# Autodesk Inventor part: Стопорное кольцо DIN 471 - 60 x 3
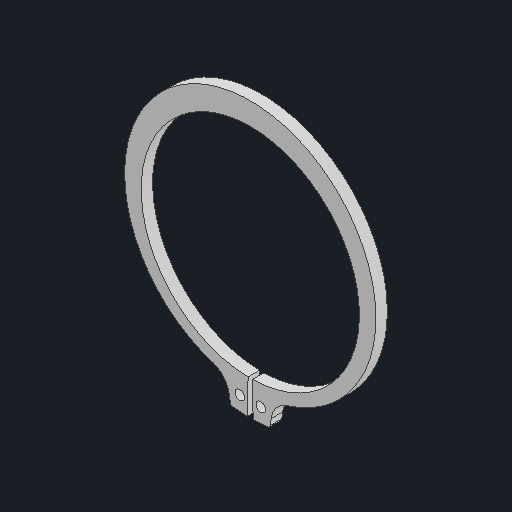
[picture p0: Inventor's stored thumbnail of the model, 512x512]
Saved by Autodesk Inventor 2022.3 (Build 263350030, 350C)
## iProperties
Created: 2020-09
Part Number: Стопорное кольцо DIN 471 - 60 x 3
Material: Типовые
Document SubType Name: Modeling
Designer: Карташов
Density: 1 g/cm^3
Appearance: По умолчанию
Title: D:\мои документы\Ирина\_WorldSkills\2020_09 ФНЧ\Module A\Участникам\GIVEN\Стопорное кольцо DIN 471 - 60 x 3.stp
Author: Дом
Sending System: Autodesk Inventor 2021
Preprocessor: ST-DEVELOPER v18.1
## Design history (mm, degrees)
feature "Твердое тело2"
node "Твердое тело1"
